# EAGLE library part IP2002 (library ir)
Synchronous Buck Multiphase Optimized BGA Power Block Source: www.irf.com/product-info/datasheets/data/ip2002.pdf
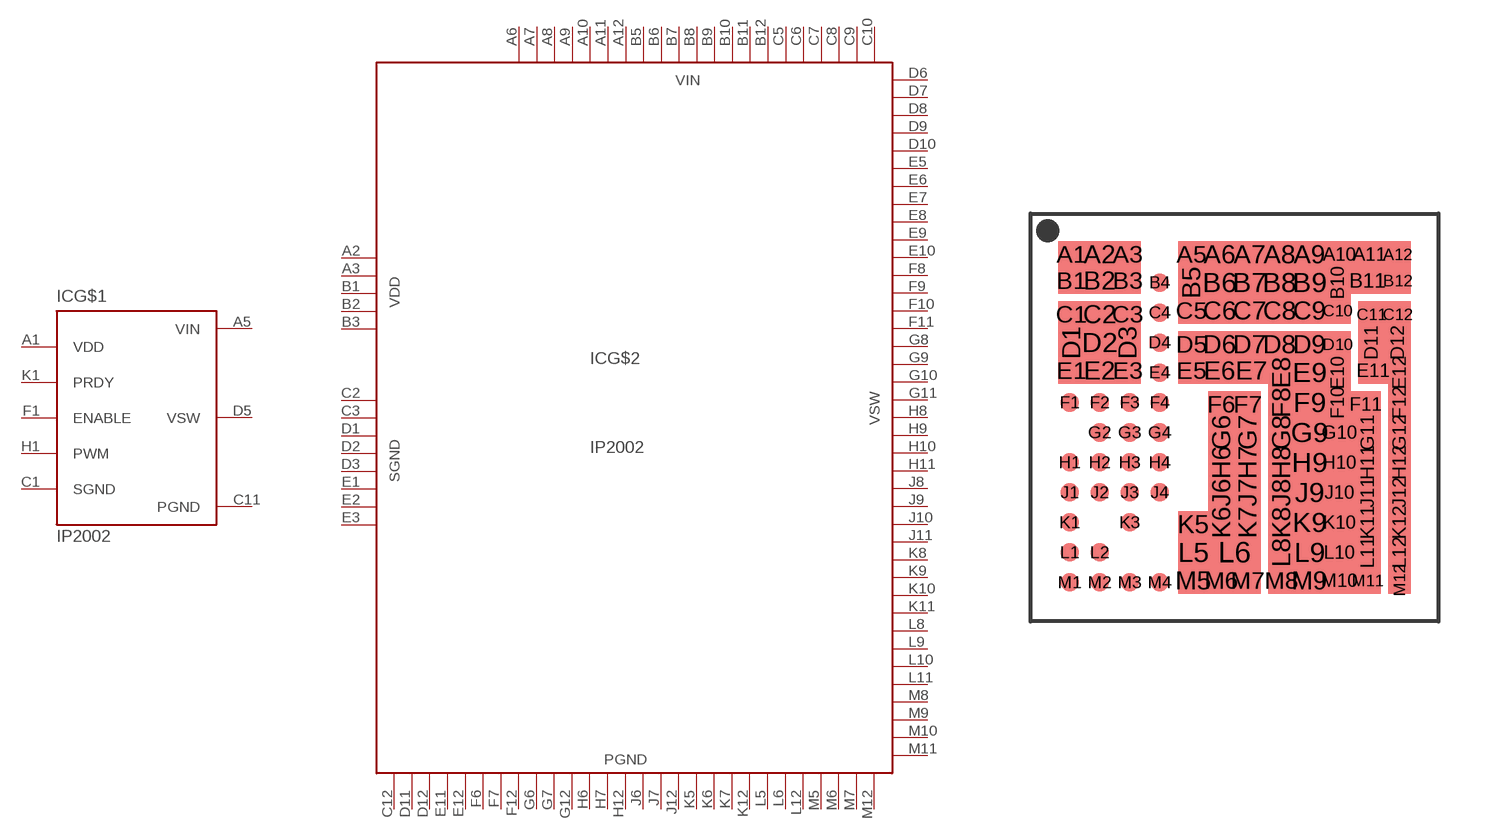
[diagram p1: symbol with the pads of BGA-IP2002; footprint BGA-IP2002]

Designator prefix IC; gates G$1=IP2002 G$2=IP2002-PWR

## IP2002 (MF: INTERNATIONAL RECTIFIER(IR); MPN: IP2002PBF; OC_FARNELL: unknown; OC_NEWARK: 11M2015)  [BGA-IP2002]
A1  G$1:VDD  pwr
A2  G$2:VDD  pwr
A3  G$2:VDD  pwr
A5  G$1:VIN  pwr
A6  G$2:VIN  pwr
A7  G$2:VIN  pwr
A8  G$2:VIN  pwr
A9  G$2:VIN  pwr
A10  G$2:VIN  pwr
A11  G$2:VIN  pwr
A12  G$2:VIN  pwr
B1  G$2:VDD  pwr
B2  G$2:VDD  pwr
B3  G$2:VDD  pwr
B5  G$2:VIN  pwr
B6  G$2:VIN  pwr
B7  G$2:VIN  pwr
B8  G$2:VIN  pwr
B9  G$2:VIN  pwr
B10  G$2:VIN  pwr
B11  G$2:VIN  pwr
B12  G$2:VIN  pwr
C1  G$1:SGND  pwr
C2  G$2:SGND  pwr
C3  G$2:SGND  pwr
C5  G$2:VIN  pwr
C6  G$2:VIN  pwr
C7  G$2:VIN  pwr
C8  G$2:VIN  pwr
C9  G$2:VIN  pwr
C10  G$2:VIN  pwr
C11  G$1:PGND  pwr
C12  G$2:PGND  pwr
D1  G$2:SGND  pwr
D2  G$2:SGND  pwr
D3  G$2:SGND  pwr
D5  G$1:VSW  pwr
D6  G$2:VSW  pwr
D7  G$2:VSW  pwr
D8  G$2:VSW  pwr
D9  G$2:VSW  pwr
D10  G$2:VSW  pwr
D11  G$2:PGND  pwr
D12  G$2:PGND  pwr
E1  G$2:SGND  pwr
E2  G$2:SGND  pwr
E3  G$2:SGND  pwr
E5  G$2:VSW  pwr
E6  G$2:VSW  pwr
E7  G$2:VSW  pwr
E8  G$2:VSW  pwr
E9  G$2:VSW  pwr
E10  G$2:VSW  pwr
E11  G$2:PGND  pwr
E12  G$2:PGND  pwr
F1  G$1:ENABLE  in
F6  G$2:PGND  pwr
F7  G$2:PGND  pwr
F8  G$2:VSW  pwr
F9  G$2:VSW  pwr
F10  G$2:VSW  pwr
F11  G$2:VSW  pwr
F12  G$2:PGND  pwr
G6  G$2:PGND  pwr
G7  G$2:PGND  pwr
G8  G$2:VSW  pwr
G9  G$2:VSW  pwr
G10  G$2:VSW  pwr
G11  G$2:VSW  pwr
G12  G$2:PGND  pwr
H1  G$1:PWM  in
H6  G$2:PGND  pwr
H7  G$2:PGND  pwr
H8  G$2:VSW  pwr
H9  G$2:VSW  pwr
H10  G$2:VSW  pwr
H11  G$2:VSW  pwr
H12  G$2:PGND  pwr
J6  G$2:PGND  pwr
J7  G$2:PGND  pwr
J8  G$2:VSW  pwr
J9  G$2:VSW  pwr
J10  G$2:VSW  pwr
J11  G$2:VSW  pwr
J12  G$2:PGND  pwr
K1  G$1:PRDY  in
K5  G$2:PGND  pwr
K6  G$2:PGND  pwr
K7  G$2:PGND  pwr
K8  G$2:VSW  pwr
K9  G$2:VSW  pwr
K10  G$2:VSW  pwr
K11  G$2:VSW  pwr
K12  G$2:PGND  pwr
L5  G$2:PGND  pwr
L6  G$2:PGND  pwr
L8  G$2:VSW  pwr
L9  G$2:VSW  pwr
L10  G$2:VSW  pwr
L11  G$2:VSW  pwr
L12  G$2:PGND  pwr
M5  G$2:PGND  pwr
M6  G$2:PGND  pwr
M7  G$2:PGND  pwr
M8  G$2:VSW  pwr
M9  G$2:VSW  pwr
M10  G$2:VSW  pwr
M11  G$2:VSW  pwr
M12  G$2:PGND  pwr

## Footprint BGA-IP2002 (pad centres in mm)
BGA Power Block Source: www.irf.com/product-info/datasheets/data/ip2002.pdf
smd 0.7 x 0.7: A1 -4.35,4.35; A3 -2.85,4.35; A5 -1.15,4.35; A12 4.35,4.35; B1 -4.35,3.65; B3 -2.85,3.65; B12 4.35,3.65; C1 -4.35,2.75; C3 -2.85,2.75; C5 -1.15,2.85; C10 2.75,2.85; C11 3.65,2.75; C12 4.35,2.75; D5 -1.15,1.95; D10 2.75,1.95; E1 -4.35,1.25; E3 -2.85,1.25; E5 -1.15,1.25; F6 -0.35,0.35; F7 0.35,0.35; M6 -0.35,-4.35; M7 0.35,-4.35; M8 1.25,-4.35; M11 3.55,-4.35
smd 0.8 x 0.7: A2 -3.6,4.35; A6 -0.4,4.35; A7 0.4,4.35; A8 1.2,4.35; A9 2,4.35; A10 2.8,4.35; A11 3.6,4.35; B2 -3.6,3.65; C2 -3.6,2.75; C6 -0.4,2.85; C7 0.4,2.85; C8 1.2,2.85; C9 2,2.85; D6 -0.4,1.95; D7 0.4,1.95; D8 1.2,1.95; D9 2,1.95; E2 -3.6,1.25; E6 -0.4,1.25; E11 3.7,1.25; F11 3.5,0.35; K5 -1.1,-2.85; M5 -1.1,-4.35; M9 2,-4.35; M10 2.8,-4.35
smd 0.5 x 0.5: B4 -2,3.6; C4 -2,2.8; D4 -2,2; E4 -2,1.2; F1 -4.4,0.4; F2 -3.6,0.4; F3 -2.8,0.4; F4 -2,0.4; G2 -3.6,-0.4; G3 -2.8,-0.4; G4 -2,-0.4; H1 -4.4,-1.2; H2 -3.6,-1.2; H3 -2.8,-1.2; H4 -2,-1.2; J1 -4.4,-2; J2 -3.6,-2; J3 -2.8,-2; J4 -2,-2; K1 -4.4,-2.8; K3 -2.8,-2.8; L1 -4.4,-3.6; L2 -3.6,-3.6; M1 -4.4,-4.4; M2 -3.6,-4.4; M3 -2.8,-4.4; M4 -2,-4.4
smd 0.7 x 0.8: B5 -1.15,3.6; B10 2.75,3.6; D1 -4.35,2; D3 -2.85,2; D11 3.65,2; D12 4.35,2; E8 1.25,1.2; E10 2.75,1.2; F8 1.25,0.4; F10 2.75,0.4; G6 -0.35,-0.4; G7 0.35,-0.4; G8 1.25,-0.4; G11 3.55,-0.4; H6 -0.35,-1.2; H7 0.35,-1.2; H8 1.25,-1.2; H11 3.55,-1.2; J6 -0.35,-2; J7 0.35,-2; J8 1.25,-2; J11 3.55,-2; K6 -0.35,-2.8; K7 0.35,-2.8; K8 1.25,-2.8; K11 3.55,-2.8; L8 1.25,-3.6; L11 3.55,-3.6
smd 0.8 x 0.8: B6 -0.4,3.6; B7 0.4,3.6; B8 1.2,3.6; B9 2,3.6; D2 -3.6,2; E9 2,1.2; F9 2,0.4; G9 2,-0.4; G10 2.8,-0.4; H9 2,-1.2; H10 2.8,-1.2; J9 2,-2; J10 2.8,-2; K9 2,-2.8; K10 2.8,-2.8; L5 -1.1,-3.6; L9 2,-3.6; L10 2.8,-3.6
smd 0.9 x 0.7: B11 3.55,3.65; E7 0.45,1.25
smd 0.6 x 0.8: E12 4.4,1.2; F12 4.4,0.4; G12 4.4,-0.4; H12 4.4,-1.2; J12 4.4,-2; K12 4.4,-2.8; L12 4.4,-3.6
smd 1.4 x 0.8: L6 0,-3.6
smd 0.6 x 0.7: M12 4.4,-4.35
